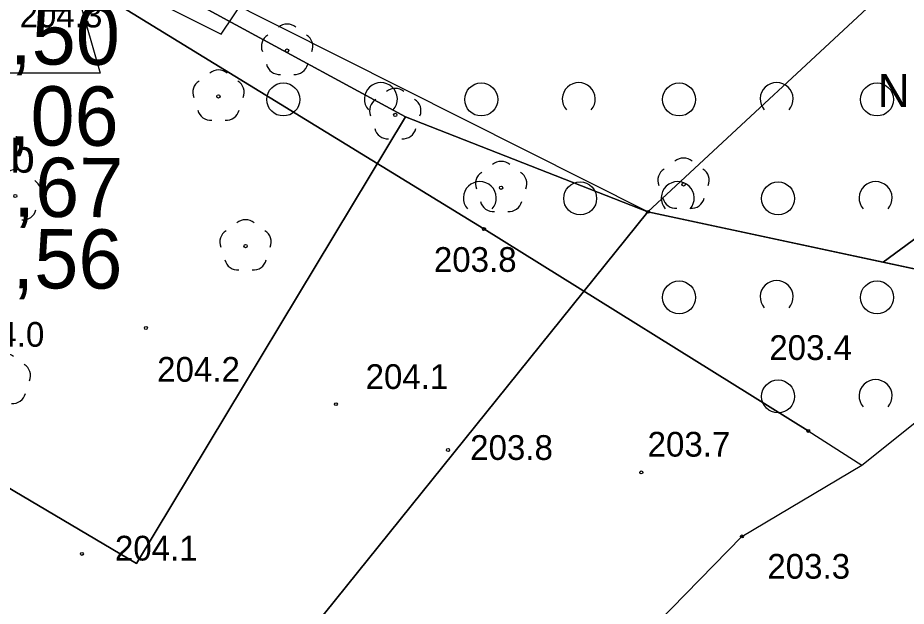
# Model space of a CAD drawing. Extents: x 6512606 to 6513006, y 6022524 to 6022728.
# Drawn here: x 6512731.97 to 6512758.91, y 6022557.42 to 6022575.25 of the extents above; entities that cross this region are included whole.
import ezdxf

# ---------------------------------------------------------------- set-up
doc = ezdxf.new("R2010")
doc.units = 0
for name, color, linetype in [('20', 7, 'Continuous'), ('203-punkt graniczny', 7, 'Continuous'), ('209-oznaczenie konturu klasyfikacyjnego', 7, 'Continuous'), ('210-oznaczenie konturu użytku gruntowego', 7, 'Continuous'), ('216-obręb ewidencyjny', 7, 'Continuous'), ('217-kontur klasyfikacyjny', 7, 'Continuous'), ('218-kontur użytku gruntowego', 7, 'Continuous'), ('219-działka ewidencyjna', 7, 'Continuous'), ('4', 7, 'Continuous'), ('Default', 7, 'Continuous'), ('drzewo liściaste', 7, 'Continuous'), ('drzewo liściaste (punkt)', 7, 'Continuous'), ('Level 47', 7, 'Continuous'), ('maxp_ramka_2', 7, 'Continuous'), ('ogrodzenie trwałe', 7, 'Continuous'), ('pikieta naturalna', 7, 'Continuous'), ('pikieta naturalna-Atr2', 7, 'Continuous'), ('punkt wysokościowy naturalny', 7, 'Continuous'), ('punkt wysokościowy naturalny-Atr2', 7, 'Continuous'), ('woda stojąca', 7, 'Continuous'), ('zadrzewienie  zakrzewienie', 7, 'Continuous')]:
    doc.layers.add(name, color=color, linetype=linetype)

# ---------------------------------------------------------------- blocks, each defined once
blk = doc.blocks.new('203')
at = {"layer": 'Default'}
blk.add_circle((0, 0), 0.45, dxfattribs=at)
blk = doc.blocks.new('PW01')
at = {"layer": 'Default'}
blk.add_circle((0, 0), 0.45, dxfattribs=at)
blk = doc.blocks.new('OP021')
at = {"layer": 'Default'}
blk.add_circle((0, 0), 0.5, dxfattribs=at)
for centre, start, end in [((0, 4), 49.272, 130.728), ((-3.8, 1.24), 121.308, 202.548), ((3.8, 1.24), 337.452, 58.692), ((-2.35, -3.24), 193.221, 274.871), ((2.35, -3.24), 265.129, 346.779)]:
    blk.add_arc(centre, 4, start, end, dxfattribs=at)
blk = doc.blocks.new('OTZK1')
at = {"layer": 'Default'}
blk.add_circle((0, 0), 5, dxfattribs=at)
blk = doc.blocks.new('OTZK2')
at = {"layer": 'Default'}
blk.add_arc((0, 0), 5, 318.85, 221.162, dxfattribs=at)

msp = doc.modelspace()

# ---------------------------------------------------------------- linework, layer by layer
at = {"layer": '20'}
for p, q in [((6512731.289, 6022584.832), (6512734.469, 6022573.571)), ((6512734.469, 6022573.571), (6512724.245, 6022573.582))]:
    msp.add_line(p, q, dxfattribs=at)
at = {"layer": '216-obręb ewidencyjny'}
for points in [[(6512728.286, 6022540.131), (6512737.69, 6022552.74), (6512751.08, 6022569.37), (6512775.81, 6022564.08), (6512780.7, 6022581.02), (6512806.2, 6022572.11), (6512806.62, 6022563.51), (6512811.41, 6022558.95), (6512818.47, 6022559.72), (6512828.23, 6022562.62), (6512858.85, 6022571.74), (6512855.78, 6022583.95), (6512853.17, 6022604.51), (6512852.25, 6022608.25), (6512838.47, 6022634.29)], [(6512824.714, 6022553.406), (6512818.47, 6022559.72), (6512811.41, 6022558.95), (6512806.62, 6022563.51), (6512806.2, 6022572.11), (6512780.7, 6022581.02), (6512775.81, 6022564.08), (6512751.08, 6022569.37)], [(6512751.08, 6022569.37), (6512737.69, 6022552.74), (6512728.286, 6022540.131)]]:
    msp.add_lwpolyline(points, dxfattribs=at)
at = {"layer": '217-kontur klasyfikacyjny'}
for points in [[(6512743.73, 6022572.25), (6512723.14, 6022583.41)], [(6512723.14, 6022583.41), (6512743.73, 6022572.25)], [(6512751.08, 6022569.37), (6512758.85, 6022576.59)], [(6512735.57, 6022558.71), (6512743.73, 6022572.25)], [(6512743.73, 6022572.25), (6512735.57, 6022558.71)], [(6512743.73, 6022572.25), (6512751.08, 6022569.37)], [(6512751.08, 6022569.37), (6512743.73, 6022572.25)], [(6512715.04, 6022570.86), (6512735.57, 6022558.71)], [(6512735.57, 6022558.71), (6512715.04, 6022570.86)], [(6512737.69, 6022552.74), (6512751.08, 6022569.37)]]:
    msp.add_lwpolyline(points, dxfattribs=at)
at = {"layer": '218-kontur użytku gruntowego'}
for points in [[(6512743.73, 6022572.25), (6512723.14, 6022583.41)], [(6512723.14, 6022583.41), (6512743.73, 6022572.25)], [(6512758.85, 6022576.59), (6512751.08, 6022569.37)], [(6512751.08, 6022569.37), (6512758.85, 6022576.59)], [(6512735.57, 6022558.71), (6512743.73, 6022572.25)], [(6512743.73, 6022572.25), (6512735.57, 6022558.71)], [(6512743.73, 6022572.25), (6512751.08, 6022569.37)], [(6512751.08, 6022569.37), (6512743.73, 6022572.25)], [(6512758.21, 6022567.84), (6512763.72, 6022571.9)], [(6512763.72, 6022571.9), (6512758.21, 6022567.84)], [(6512715.04, 6022570.86), (6512735.57, 6022558.71)], [(6512735.57, 6022558.71), (6512715.04, 6022570.86)], [(6512737.69, 6022552.74), (6512751.08, 6022569.37)], [(6512751.08, 6022569.37), (6512737.69, 6022552.74)], [(6512751.08, 6022569.37), (6512758.21, 6022567.84)], [(6512758.21, 6022567.84), (6512751.08, 6022569.37)], [(6512758.21, 6022567.84), (6512775.81, 6022564.08)], [(6512775.81, 6022564.08), (6512758.21, 6022567.84)]]:
    msp.add_lwpolyline(points, dxfattribs=at)
at = {"layer": '219-działka ewidencyjna'}
for points in [[(6512751.08, 6022569.37), (6512723.14, 6022583.41)], [(6512758.85, 6022576.59), (6512751.08, 6022569.37)], [(6512737.69, 6022552.74), (6512751.08, 6022569.37)], [(6512775.81, 6022564.08), (6512751.08, 6022569.37)]]:
    msp.add_lwpolyline(points, dxfattribs=at)
at = {"layer": '4'}
for points in [[(6512751.08, 6022569.37), (6512723.14, 6022583.41)], [(6512758.85, 6022576.59), (6512751.08, 6022569.37)], [(6512737.69, 6022552.74), (6512751.08, 6022569.37)], [(6512775.81, 6022564.08), (6512751.08, 6022569.37)]]:
    msp.add_lwpolyline(points, dxfattribs=at)
at = {"layer": 'maxp_ramka_2'}
for p, q in [((6512738.139, 6022574.754), (6512746.53, 6022587.278)), ((6512723.442, 6022582.139), (6512738.139, 6022574.754))]:
    msp.add_line(p, q, dxfattribs=at)
at = {"layer": 'ogrodzenie trwałe'}
msp.add_lwpolyline([(6512755.94, 6022562.73), (6512746.11, 6022568.85), (6512734.85, 6022575.76), (6512722.94, 6022583.56), (6512729.52, 6022596.18), (6512735.87, 6022607.95), (6512736.94, 6022619.99)], dxfattribs=at)
at = {"layer": 'woda stojąca'}
msp.add_lwpolyline([(6512741.02, 6022546.93), (6512746.68, 6022552.11), (6512753.93, 6022559.53), (6512757.57, 6022561.69), (6512765.47, 6022568.01), (6512770.86, 6022573.28), (6512769.34, 6022577.71), (6512768.52, 6022578.94)], dxfattribs=at)
at = {"layer": 'zadrzewienie  zakrzewienie'}
msp.add_lwpolyline([(6512722.94, 6022583.56), (6512734.85, 6022575.76), (6512746.11, 6022568.85), (6512755.94, 6022562.73), (6512757.57, 6022561.69), (6512765.47, 6022568.01)], dxfattribs=at)

# ---------------------------------------------------------------- block references
at = {"layer": '203-punkt graniczny', "xscale": 0.1, "yscale": 0.10000000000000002}
msp.add_blockref('203', (6512751.08, 6022569.37), dxfattribs=at)
at = {"layer": 'drzewo liściaste', "xscale": 0.1, "yscale": 0.10000000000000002}
for p in [(6512740.14, 6022574.26), (6512738.06, 6022572.87), (6512743.42, 6022572.31), (6512746.63, 6022570.1), (6512731.9, 6022569.85), (6512738.88, 6022568.33), (6512731.58, 6022564.28)]:
    msp.add_blockref('OP021', p, dxfattribs=at)
at = {"layer": 'drzewo liściaste (punkt)', "xscale": 0.1, "yscale": 0.10000000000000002}
msp.add_blockref('OP021', (6512752.16, 6022570.2), dxfattribs=at)
at = {"layer": 'pikieta naturalna', "xscale": 0.1, "yscale": 0.10000000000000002}
for p in [(6512746.11, 6022568.85), (6512735.86, 6022565.85), (6512755.94, 6022562.73), (6512745.02, 6022562.15), (6512750.88, 6022561.47), (6512753.93, 6022559.53), (6512733.92, 6022559)]:
    msp.add_blockref('PW01', p, dxfattribs=at)
at = {"layer": 'punkt wysokościowy naturalny', "xscale": 0.1, "yscale": 0.10000000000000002}
msp.add_blockref('PW01', (6512741.62, 6022563.54), dxfattribs=at)
at = {"layer": 'zadrzewienie  zakrzewienie', "xscale": 0.1, "yscale": 0.10000000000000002}
for name, p in [('OTZK1', (6512740.026, 6022572.776)), ('OTZK2', (6512742.984, 6022572.787)), ('OTZK1', (6512746.026, 6022572.776)), ('OTZK2', (6512748.984, 6022572.787)), ('OTZK1', (6512752.026, 6022572.776)), ('OTZK2', (6512754.984, 6022572.787)), ('OTZK1', (6512758.026, 6022572.776)), ('OTZK2', (6512745.984, 6022569.787)), ('OTZK2', (6512751.984, 6022569.787)), ('OTZK2', (6512757.984, 6022569.787)), ('OTZK1', (6512749.026, 6022569.776)), ('OTZK1', (6512755.026, 6022569.776)), ('OTZK1', (6512752.026, 6022566.776)), ('OTZK2', (6512754.984, 6022566.787)), ('OTZK1', (6512758.026, 6022566.776)), ('OTZK1', (6512755.026, 6022563.776)), ('OTZK2', (6512757.984, 6022563.787))]:
    msp.add_blockref(name, p, dxfattribs=at)

# ---------------------------------------------------------------- texts
at = {"layer": '209-oznaczenie konturu klasyfikacyjnego'}
msp.add_text('RIVb', height=1, dxfattribs=at).set_placement((6512729.52, 6022570.56))
at = {"layer": '210-oznaczenie konturu użytku gruntowego'}
msp.add_text('N', height=1, dxfattribs=at).set_placement((6512758.05, 6022572.55))
at = {"layer": 'Level 47'}
for s, p in [('t=204,50', (6512725.646, 6022573.869)), ('tł=203,06', (6512725.075, 6022571.417)), ('wl=201,67', (6512724.147, 6022569.257)), ('d=200,56', (6512725.054, 6022567.087))]:
    msp.add_text(s, height=1.7971, rotation=359.7281, dxfattribs=at).set_placement(p)
at = {"layer": 'pikieta naturalna-Atr2'}
for s, p in [('204.3', (6512732.03, 6022574.96)), ('203.8', (6512744.59, 6022567.55)), ('203.4', (6512754.76, 6022564.88)), ('204.2', (6512736.2, 6022564.22)), ('203.8', (6512745.69, 6022561.85)), ('203.7', (6512751.07, 6022561.95)), ('204.1', (6512734.92, 6022558.8)), ('203.3', (6512754.7, 6022558.25))]:
    msp.add_text(s, height=0.75, dxfattribs=at).set_placement(p)
at = {"layer": 'punkt wysokościowy naturalny-Atr2'}
for s, p in [('204.0', (6512730.27, 6022565.28)), ('204.1', (6512742.52, 6022564))]:
    msp.add_text(s, height=0.75, dxfattribs=at).set_placement(p)

doc.saveas('drawing.dxf')
